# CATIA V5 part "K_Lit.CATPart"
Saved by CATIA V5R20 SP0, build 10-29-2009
Part number: Lit
Publications: "Plansymétrieensemble", "Arête", "hauteurexcroissance", "Droite_base_lit2", "Face", "rayonaxepivot", "Face2"
Bounding box of the stored display mesh (mm): x 0 to 300, y -45 to 15, z 0 to 1000
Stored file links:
  G:\Khaled_CFAO_2011\SIL\SIL_GR2\zthiebault\Khaled\CAD_ThinkMOTION\K_Lit.CATPart
  F:\Projet Thinkmotion\Catia\FINAL\HabillageFinal.CATProduct
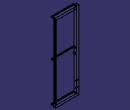
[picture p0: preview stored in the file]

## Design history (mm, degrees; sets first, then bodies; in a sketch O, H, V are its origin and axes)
Parameters
  distpocheint = 30 mm
  hauteurexcroissance = 30 mm
  rayonaxepivot = 2 mm
External parameters (linked from other documents)
  External.largeurcadre = 300 mm
  External.Longueurcadre = 1000 mm
Set1
  Point1 "Point_base_lit1": linked copy from another document
  Point2 "Point_base_lit2": linked copy from another document
  Point3 "Point_base_lit3": linked copy from another document
  Point4 "Point_base_lit4": linked copy from another document
  Point5 "Point_base_lit5": linked copy from another document
  Plane1 "Plan_base_lit2": linked copy from another document
  Line1 "Droite_base_lit2": linked copy from another document
  Point6 "Point_base_lit6": linked copy from another document
  Line2 "Droite_base_lit1": linked copy from another document
  Line3 "Droite_base_lit4": linked copy from another document
Set2
  DatumSurface1
  Point7: type OnCurve, Support Line1, Length 15 {= distpocheint /2}
  Plane2: type OffsetPt, RefPlane xy-plane, RefPoint Point2
  Point8: type OnCurve, Support Line2, Length 15 {= distpocheint /2}
  Plane3: type OffsetPt, RefPlane Plane2, RefPoint Point8
  Point9: type OnCurve, Support Line3, Length 150 {= External.largeurcadre /2}
  Plane4: type OffsetPt, RefPlane xy-plane, RefPoint Point9
  Plane5 "Planmoitiehauteur": type Offset, RefPlane Plane4, Offset 500 {= External.Longueurcadre /2}
  Plane6: type Offset, RefPlane Plane5, Offset 250 {= External.Longueurcadre /4}
  Plane7 "Plansymétrieensemble": type OffsetPt, RefPlane yz-plane, RefPoint vertex of Line3
Body1 (main body)
  Sketch1 on zx-plane, origin (0, 0, 0), H (-1, 0, 0), V (0, 0, 1)
    point P1 (-300, 1000)
    line L1 (-300, 1000) -> (0, 1000)
    line L2 (0, 1000) -> (0, 0)
    line L3 (0, 0) -> (-300, 0)
    line L4 (-300, 0) -> (-300, 1000)
    point P2 (0, 1000)
    point P3 (0, 0)
    reference projected point E1 (-300, 1000) from Point1
    reference projected point E2 (0, 1000) from Point2
    reference projected point E3 (0, 0) from Point3
    line L5 (-285, 970) -> (-30, 970)
    line L6 (-30, 970) -> (-30, 30)
    line L7 (-30, 30) -> (-285, 30)
    line L8 (-285, 30) -> (-285, 970)
    distance L5 L1 = 30 {= distpocheint}
    distance L7 L3 = 30 {= distpocheint}
    distance L6 L2 = 30 {= distpocheint}
    distance L8 L4 = 15 {= distpocheint /2}
    horizontal: L1 H, L3 H, L5 H, L7 H
    vertical: L2 V, L4 V, L6 V, L8 V
    coincidence: P1 E1, P2 E2, P3 E3
  Pad1: profile Sketch1, direction (0, 1, 0), length 15 {= distpocheint /2}, opposite side length 15 {= distpocheint /2}
  Sketch2 on face of Pad1 from Sketch1.L6, origin (30, -2.7236, 148.2378), H (0, 1, 0), V (0, 0, 1)
    point P1 (2.6892, 11.7622)
    reference projected point E1 (2.6892, 11.7622) from Point4
    coincidence: P1 E1
  Hole1: placed by Sketch2, at (30, -0.0344, 160) direction (-1, 0, 0), diameter 10, through (limit type 6)
  Sketch3 on face of Pad1 from Sketch1.L6, origin (30, -1.7043, 113.042), H (0, 1, 0), V (0, 0, 1)
    point P1 (1.6871, -33.042)
    reference projected point E1 (1.6871, -33.042) from Point5
    coincidence: P1 E1
  Hole2: placed by Sketch3, at (30, -0.0172, 80) direction (-1, 0, 0), diameter 10, through (limit type 6)
  Sketch4 on Plane1, origin (15.5, 0, 0), H (0, 1, 0), V (0, 0, 1)
    point P1 (-15.0969, 464.9968)
    line L1 (-15.0969, 464.9968) -> (-46.7196, 449.9968)
    line L2 (-46.7196, 449.9968) -> (-15.0969, 434.9968)
    line L3 (-15.0969, 434.9968) -> (-15.0969, 464.9968)
    reference projected point E1 (-15.0969, 449.9968) from Point7
    reference projected point E2 (-15.0969, 449.9968) from Point7
    length L1 = 35
    length L3 = 30 {= hauteurexcroissance}
    length L2 = 35 {= Sketch4.length(L1)}
    distance P1 E2 = 15 {= Sketch4.length(L3) /2}
    vertical: L3 V
    coincidence: L3 E1
  Pad2: profile Sketch4, direction (1, 0, 0), length 1.5, opposite side length 1.5
  Fillet1: radius 4, on edge [face of Pad2 from Sketch4.L1 | face of Pad2 from Sketch4.L2]
  Sketch5 on start face of Pad2, origin (14, 0, 0), H (0, -1, 0), V (0, 0, 1)
    circle A1 centre (37.3699, 449.992) radius 2
    point P1 (37.3699, 449.992)
    reference projected point E1 (37.3699, 449.992) from Point6
    radius A1 = 2 {= rayonaxepivot}
    coincidence: P1 E1
  Pad3: profile Sketch5, direction (-1, 0, 0), length 11, opposite side length 14
  Sketch6 on Plane3, origin (0, 0, 985), H (1, 0, 0), V (0, 1, 0)
    line L1 (10, -15) -> (10, -45)
    line L2 (10, -45) -> (300, -45)
    line L3 (300, -45) -> (300, -15)
    line L4 (300, -15) -> (290, -15)
    line L5 (290, -15) -> (290, -35)
    line L6 (290, -35) -> (20, -35)
    line L7 (20, -35) -> (20, -15)
    line L8 (20, -15) -> (10, -15)
    reference projected line E1 (0, -0.0969) -> (0, -40.0969) from Line1
    reference projected point E2 (300, -0.2153) from Point1
    reference projected point E3 (300, -0.2153) from Point1
    reference intersected line E4 (300, -15) -> (0, -15) from start face of Pad1
    length L8 = 10 {= distpocheint /3}
    distance L1 E1 = 10 {= distpocheint /3}
    distance L8 L2 = 30
    distance L6 L2 = 10 {= Sketch6.length(L8)}
    distance L5 E2 = 10 {= distpocheint /3}
    vertical: L1 V, L3 V, L5 V, L7 V
    horizontal: L2 H, L4 H, L6 H, L8 H
    coincidence: L3 E3, L8 L4, L8 E4
  Pad4: profile Sketch6, direction (0, 0, 1), length 5, opposite side length 5
  Mirror1: of Pad4, Sketch6, about Plane5
  Mirror2: of Pad4, Sketch6, about Plane6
